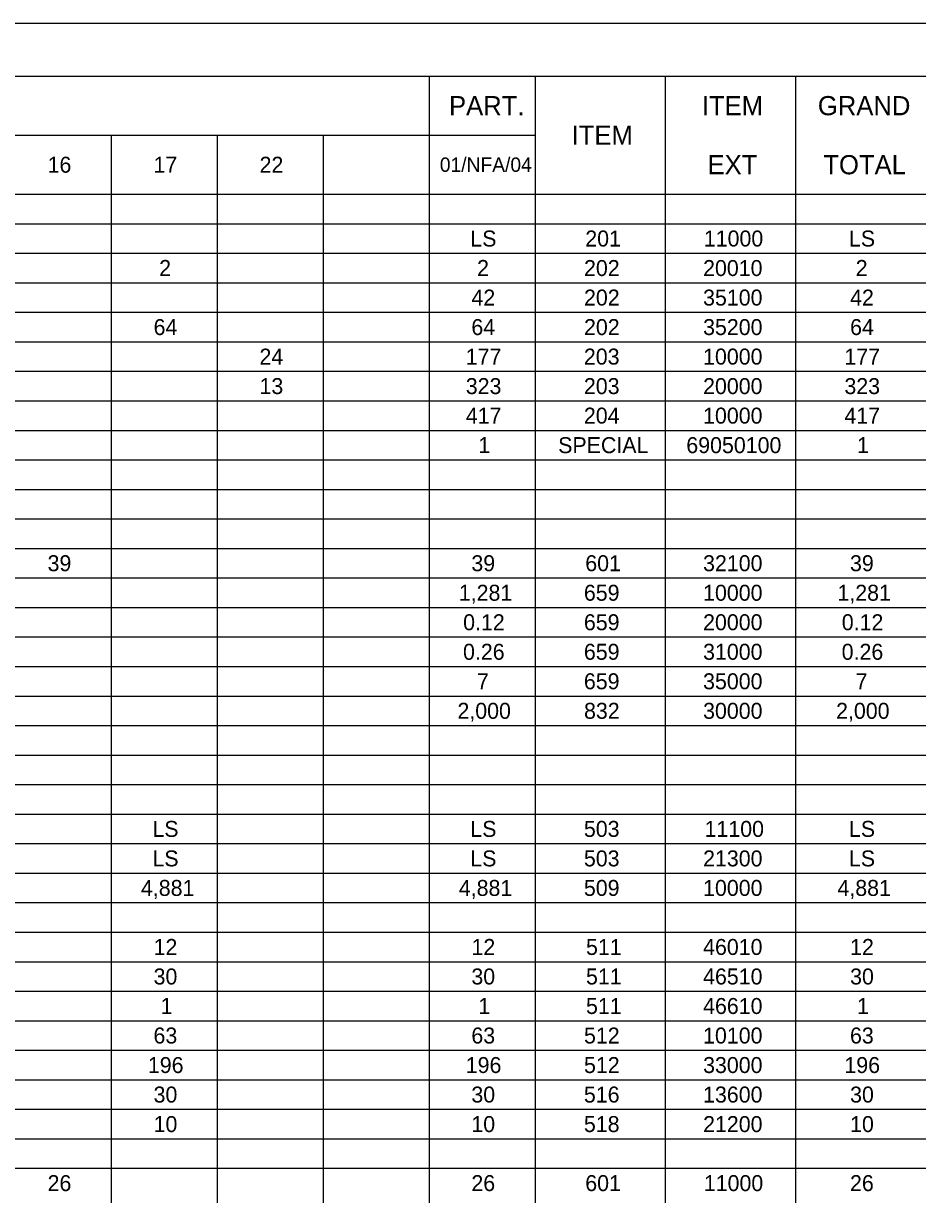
# Model space of a CAD drawing. Extents: x 0 to 34, y 0 to 22.
# Drawn here: x 8.7 to 17.18, y 10.89 to 22 of the extents above; entities that cross this region are included whole.
import ezdxf

# ---------------------------------------------------------------- set-up
doc = ezdxf.new("R2010")
doc.units = 0
for name, color, linetype in [('SH_Border', 7, 'Continuous'), ('SH_Cut_Line', 7, 'Continuous'), ('SH_Text', 7, 'Continuous')]:
    doc.layers.add(name, color=color, linetype=linetype)

msp = doc.modelspace()

# ---------------------------------------------------------------- linework, layer by layer
at = {"layer": 'SH_Border'}
msp.add_lwpolyline([(1.5, 21.5), (33.5, 21.5), (33.5, 0.5), (1.5, 0.5)], close=True, dxfattribs=at)
at = {"layer": 'SH_Cut_Line'}
msp.add_lwpolyline([(0, 0), (34, 0), (34, 22), (0, 22)], close=True, dxfattribs=at)
at = {"layer": 'SH_Text'}
for p, q in [((1.5, 21.5), (32, 21.5)), ((12.55, 21.5), (12.55, 0.5)), ((13.555, 21.5), (13.555, 0.5)), ((14.79, 21.5), (14.79, 0.5)), ((16.025, 21.5), (16.025, 0.5)), ((1.5, 20.94), (13.555, 20.94)), ((9.537, 20.94), (9.537, 0.5)), ((10.541, 20.94), (10.541, 0.5)), ((11.546, 20.94), (11.546, 0.5)), ((1.5, 20.38), (32, 20.38)), ((1.5, 20.1), (32, 20.1)), ((1.5, 19.82), (32, 19.82)), ((1.5, 19.54), (32, 19.54)), ((1.5, 19.26), (32, 19.26)), ((1.5, 18.98), (32, 18.98)), ((1.5, 18.7), (32, 18.7)), ((1.5, 18.42), (32, 18.42)), ((1.5, 18.14), (32, 18.14)), ((1.5, 17.86), (32, 17.86)), ((1.5, 17.58), (32, 17.58)), ((1.5, 17.3), (32, 17.3)), ((1.5, 17.02), (32, 17.02)), ((1.5, 16.74), (32, 16.74)), ((1.5, 16.46), (32, 16.46)), ((1.5, 16.18), (32, 16.18)), ((1.5, 15.9), (32, 15.9)), ((1.5, 15.62), (32, 15.62)), ((1.5, 15.34), (32, 15.34)), ((1.5, 15.06), (32, 15.06)), ((1.5, 14.78), (32, 14.78)), ((1.5, 14.5), (32, 14.5)), ((1.5, 14.22), (32, 14.22)), ((1.5, 13.94), (32, 13.94)), ((1.5, 13.66), (32, 13.66)), ((1.5, 13.38), (32, 13.38)), ((1.5, 13.1), (32, 13.1)), ((1.5, 12.82), (32, 12.82)), ((1.5, 12.54), (32, 12.54)), ((1.5, 12.26), (32, 12.26)), ((1.5, 11.98), (32, 11.98)), ((1.5, 11.7), (32, 11.7)), ((1.5, 11.42), (32, 11.42)), ((1.5, 11.14), (32, 11.14))]:
    msp.add_line(p, q, dxfattribs=at)

# ---------------------------------------------------------------- texts
for s, height, p in [('PART.', 0.1818, (12.739, 21.129)), ('ITEM', 0.1818, (15.136, 21.129)), ('GRAND', 0.1818, (16.236, 21.129)), ('ITEM', 0.1818, (13.901, 20.849)), ('16', 0.1515, (8.933, 20.584)), ('17', 0.1515, (9.937, 20.584)), ('22', 0.1515, (10.943, 20.584)), ('01/NFA/04', 0.1364, (12.652, 20.592)), ('EXT', 0.1818, (15.19, 20.569)), ('TOTAL', 0.1818, (16.288, 20.569)), ('LS', 0.1515, (12.941, 19.884)), ('201', 0.1515, (14.031, 19.884)), ('11000', 0.1515, (15.155, 19.884)), ('LS', 0.1515, (16.531, 19.884)), ('2', 0.152, (9.991, 19.604)), ('2', 0.152, (13.005, 19.604)), ('202', 0.1515, (14.019, 19.604)), ('20010', 0.1515, (15.148, 19.604)), ('2', 0.152, (16.595, 19.604)), ('42', 0.1515, (12.952, 19.324)), ('202', 0.1515, (14.019, 19.324)), ('35100', 0.1515, (15.148, 19.324)), ('42', 0.1515, (16.542, 19.324)), ('64', 0.1515, (9.938, 19.044)), ('64', 0.1515, (12.951, 19.044)), ('202', 0.1515, (14.019, 19.044)), ('35200', 0.1515, (15.148, 19.044)), ('64', 0.1515, (16.542, 19.044)), ('24', 0.1515, (10.942, 18.764)), ('177', 0.1515, (12.898, 18.764)), ('203', 0.1515, (14.018, 18.764)), ('10000', 0.1515, (15.148, 18.764)), ('177', 0.1515, (16.488, 18.764)), ('13', 0.1515, (10.942, 18.484)), ('323', 0.1515, (12.898, 18.484)), ('203', 0.1515, (14.018, 18.484)), ('20000', 0.1515, (15.148, 18.484)), ('323', 0.1515, (16.488, 18.484)), ('417', 0.1515, (12.898, 18.204)), ('204', 0.1515, (14.018, 18.204)), ('10000', 0.1515, (15.148, 18.204)), ('417', 0.1515, (16.488, 18.204)), ('1', 0.152, (13.017, 17.924)), ('SPECIAL', 0.1515, (13.774, 17.924)), ('69050100', 0.1515, (14.989, 17.924)), ('1', 0.152, (16.608, 17.924)), ('39', 0.1515, (8.933, 16.804)), ('39', 0.1515, (12.951, 16.804)), ('601', 0.1515, (14.031, 16.804)), ('32100', 0.1515, (15.148, 16.804)), ('39', 0.1515, (16.541, 16.804)), ('1,281', 0.1515, (12.832, 16.524)), ('659', 0.1515, (14.018, 16.524)), ('10000', 0.1515, (15.148, 16.524)), ('1,281', 0.1515, (16.422, 16.524)), ('0.12', 0.1515, (12.873, 16.244)), ('659', 0.1515, (14.018, 16.244)), ('20000', 0.1515, (15.148, 16.244)), ('0.12', 0.1515, (16.463, 16.244)), ('0.26', 0.1515, (12.872, 15.964)), ('659', 0.1515, (14.018, 15.964)), ('31000', 0.1515, (15.148, 15.964)), ('0.26', 0.1515, (16.462, 15.964)), ('7', 0.152, (13.004, 15.684)), ('659', 0.1515, (14.018, 15.684)), ('35000', 0.1515, (15.148, 15.684)), ('7', 0.152, (16.594, 15.684)), ('2,000', 0.1515, (12.819, 15.404)), ('832', 0.1515, (14.019, 15.404)), ('30000', 0.1515, (15.148, 15.404)), ('2,000', 0.1515, (16.409, 15.404)), ('LS', 0.1515, (9.927, 14.284)), ('LS', 0.1515, (12.941, 14.284)), ('503', 0.1515, (14.018, 14.284)), ('11100', 0.1515, (15.162, 14.284)), ('LS', 0.1515, (16.531, 14.284)), ('LS', 0.1515, (9.927, 14.004)), ('LS', 0.1515, (12.941, 14.004)), ('503', 0.1515, (14.018, 14.004)), ('21300', 0.1515, (15.148, 14.004)), ('LS', 0.1515, (16.531, 14.004)), ('4,881', 0.1515, (9.818, 13.724)), ('4,881', 0.1515, (12.832, 13.724)), ('509', 0.1515, (14.018, 13.724)), ('10000', 0.1515, (15.148, 13.724)), ('4,881', 0.1515, (16.422, 13.724)), ('12', 0.1515, (9.938, 13.164)), ('12', 0.1515, (12.952, 13.164)), ('511', 0.1515, (14.038, 13.164)), ('46010', 0.1515, (15.148, 13.164)), ('12', 0.1515, (16.542, 13.164)), ('30', 0.1515, (9.938, 12.884)), ('30', 0.1515, (12.951, 12.884)), ('511', 0.1515, (14.038, 12.884)), ('46510', 0.1515, (15.148, 12.884)), ('30', 0.1515, (16.542, 12.884)), ('1', 0.152, (10.004, 12.604)), ('1', 0.152, (13.017, 12.604)), ('511', 0.1515, (14.038, 12.604)), ('46610', 0.1515, (15.148, 12.604)), ('1', 0.152, (16.608, 12.604)), ('63', 0.1515, (9.937, 12.324)), ('63', 0.1515, (12.951, 12.324)), ('512', 0.1515, (14.019, 12.324)), ('10100', 0.1515, (15.148, 12.324)), ('63', 0.1515, (16.541, 12.324)), ('196', 0.1515, (9.884, 12.044)), ('196', 0.1515, (12.898, 12.044)), ('512', 0.1515, (14.019, 12.044)), ('33000', 0.1515, (15.148, 12.044)), ('196', 0.1515, (16.488, 12.044)), ('30', 0.1515, (9.938, 11.764)), ('30', 0.1515, (12.951, 11.764)), ('516', 0.1515, (14.018, 11.764)), ('13600', 0.1515, (15.148, 11.764)), ('30', 0.1515, (16.542, 11.764)), ('10', 0.1515, (9.938, 11.484)), ('10', 0.1515, (12.951, 11.484)), ('518', 0.1515, (14.018, 11.484)), ('21200', 0.1515, (15.148, 11.484)), ('10', 0.1515, (16.542, 11.484)), ('26', 0.1515, (8.933, 10.924)), ('26', 0.1515, (12.951, 10.924)), ('601', 0.1515, (14.031, 10.924)), ('11000', 0.1515, (15.155, 10.924)), ('26', 0.1515, (16.541, 10.924))]:
    msp.add_text(s, height=height, dxfattribs=at).set_placement(p)

doc.saveas('drawing.dxf')
